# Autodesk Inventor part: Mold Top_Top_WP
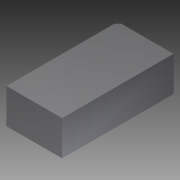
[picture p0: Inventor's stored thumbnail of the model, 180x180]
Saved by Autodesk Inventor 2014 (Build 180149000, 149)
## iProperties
Created: 2009-12
Part Number: Mold Top_Top_WP
Document SubType Name: Modeling
Designer: gaom
Density: 1 g/cm^3
Material: Generic
Appearance: Light Gray
Xmin: -40.000 mm
Ymin: -80.000 mm
Zmin: -25.000 mm
Xmax: 40.000 mm
Ymax: 80.000 mm
Zmax: 25.000 mm
d0: -25.000 mm
d1: 40.000 mm
d2: 40.000 mm
d3: 80.000 mm
d4: 80.000 mm
d5: 50.000 mm
d6: 0.00 deg
d7: 5.000 mm
Author: gaom
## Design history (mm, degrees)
sketch "Sketch1"
  geometry: L1 (-40, 80)-(40, 80); L2 (40, 80)-(40, -80); L3 (40, -80)-(-40, -80); L4 (-40, -80)-(-40, 80); 1 further point
  constraints: 8 end point, 2 parallel, 1 horizontal, 1 perpendicular, 1 other
  dimensions: "d1" = 40 distance from line of L4 point (0, 0) (= -Xmin); "d2" = 40 distance from line of L2 point (0, 0) (= Xmax); "d3" = 80 distance from line of L3 point (0, 0) (= -Ymin); "d4" = 80 distance from line of L1 point (0, 0) (= Ymax)
extrude "Extrusion1" join sketch "Sketch1" distance "d5" = 50 (= Zmax - Zmin); taper "d6" = 0 deg
chamfer "Chamfer1" distance "d7" = 5; stored, may be unused: second distance "d8" = 5, angle "d9" = 45 deg
body "Solid1"
other parameters: "Xmin" = -40 [user parameter; used in 1 equation term], "Ymin" = -80 [user parameter; used in 1 equation term], "Zmin" = -25 [user parameter; used in 1 equation term], "Xmax" = 40 [user parameter; used in 1 equation term], "Ymax" = 80 [user parameter; used in 1 equation term], "Zmax" = 25 [user parameter; used in 1 equation term], "d0" = -25
